// Mitsubishi GX Works2 project: PJT07_12_PLC02変更後(20220606_01)   PLC: Q03UDV

FUNCTION_BLOCK Alarm_FB
VAR_INPUT
  IB_Alarm : BOOL;  (* 入力@警報発生(0:-/1:発生) *)
END_VAR
VAR
  VT_AlarmDelayTimer : TIMER;  (* 内部@異常入力ﾃﾞｨﾚｲﾀｲﾏ *)
END_VAR
VAR_INPUT
  IW_DelayTimerVal : INT;  (* 入力@ﾃﾞｨﾚｲﾀｲﾏ値 *)
END_VAR
VAR_OUTPUT
  OB_AlarmHolding : BOOL;  (* 出力@ｱﾗｰﾑ自己保持(0:-/1:保持) *)
END_VAR
VAR_INPUT
  IB_AlarmResetPB : BOOL;  (* 入力@警報ﾘｾｯﾄPB(0:-/1:ﾘｾｯﾄ) *)
END_VAR
VAR
  VT_BuzzerStopTimer : TIMER;  (* 内部@ﾌﾞｻﾞｰｽﾄｯﾌﾟﾀｲﾏ *)
END_VAR
VAR_INPUT
  IW_BzStopTVal : INT;  (* 入力@ﾌﾞｻﾞｰｽﾄｯﾌﾟﾀｲﾏ値 *)
END_VAR
VAR
  VB_BuzzerStopFLG : BOOL;  (* 内部@ﾌﾞｻﾞｰｽﾄｯﾌﾟﾃﾞﾊﾞｲｽ(0:-/1:停止) *)
END_VAR
VAR_OUTPUT
  OB_DisplayFLG : BOOL;  (* 出力@ｱﾗｰﾑ表示ﾃﾞﾊﾞｲｽ(0:点滅/1:点灯) *)
END_VAR
VAR_INPUT
  IB_BuzzerStopPB : BOOL;  (* 入力@ﾌﾞｻﾞｰｽﾄｯﾌﾟPB(0:-/1:ｽﾄｯﾌﾟ) *)
END_VAR
VAR_OUTPUT
  OB_BuzzerFLG : BOOL;  (* 出力@ﾌﾞｻﾞｰﾌﾗｸﾞ *)
END_VAR
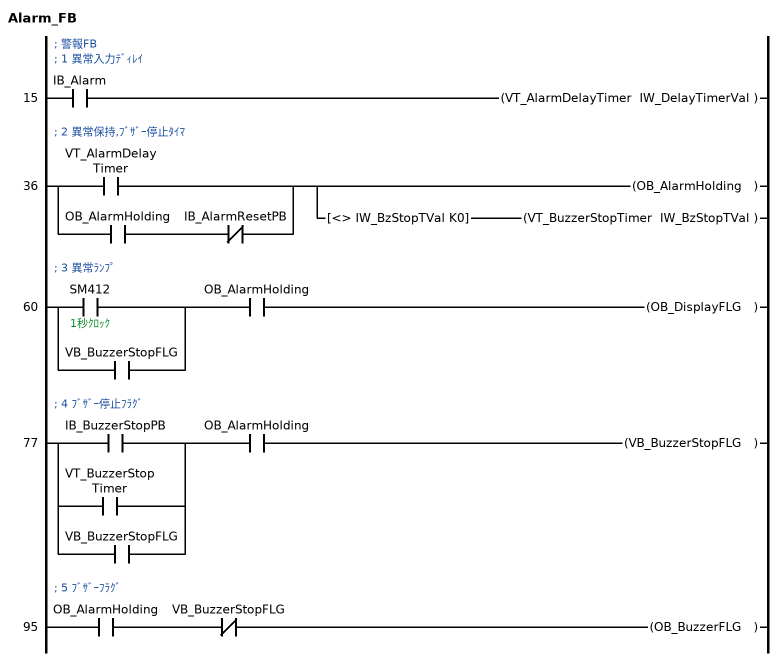
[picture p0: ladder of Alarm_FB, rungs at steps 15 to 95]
; 警報FB
; 1 異常入力ﾃﾞｨﾚｲ
15    LD      IB_Alarm
      OUT     VT_AlarmDelayTimer IW_DelayTimerVal
; 2 異常保持,ﾌﾞｻﾞｰ停止ﾀｲﾏ
36    LD      VT_AlarmDelayTimer
      LD      OB_AlarmHolding
      ANI     IB_AlarmResetPB
      ORB
      OUT     OB_AlarmHolding
      AND<>   IW_BzStopTVal K0
      OUT     VT_BuzzerStopTimer IW_BzStopTVal
; 3 異常ﾗﾝﾌﾟ
60    LD      SM412  ; 1秒ｸﾛｯｸ
      OR      VB_BuzzerStopFLG
      AND     OB_AlarmHolding
      OUT     OB_DisplayFLG
; 4 ﾌﾞｻﾞｰ停止ﾌﾗｸﾞ
77    LD      IB_BuzzerStopPB
      OR      VT_BuzzerStopTimer
      OR      VB_BuzzerStopFLG
      AND     OB_AlarmHolding
      OUT     VB_BuzzerStopFLG
; 5 ﾌﾞｻﾞｰﾌﾗｸﾞ
95    LD      OB_AlarmHolding
      ANI     VB_BuzzerStopFLG
      OUT     OB_BuzzerFLG
END_FUNCTION_BLOCK

PROGRAM 11_Alarm
VAR
  Alarm_FB_1 : Alarm_FB;
  Alarm_FB_2 : Alarm_FB;
END_VAR
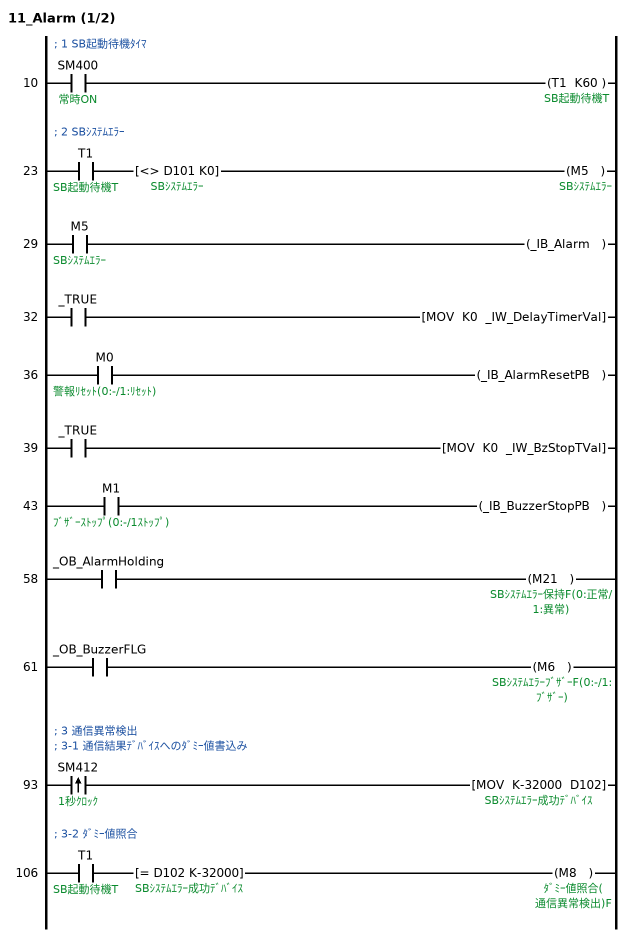
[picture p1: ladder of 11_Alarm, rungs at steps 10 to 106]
; 1 SB起動待機ﾀｲﾏ
10    LD      SM400  ; 常時ON
      OUT     T1 K60  ; SB起動待機T
; 2 SBｼｽﾃﾑｴﾗｰ
23    LD      T1  ; SB起動待機T
      AND<>   D101 K0  ; SBｼｽﾃﾑｴﾗｰ
      OUT     M5  ; SBｼｽﾃﾑｴﾗｰ
; FB BLK START Alarm_FB(Alarm_FB_1)
29    LD      M5  ; SBｼｽﾃﾑｴﾗｰ
      OUT     _IB_Alarm
32    LD      _TRUE
      MOV     K0 _IW_DelayTimerVal
36    LD      M0  ; 警報ﾘｾｯﾄ(0:-/1:ﾘｾｯﾄ)
      OUT     _IB_AlarmResetPB
39    LD      _TRUE
      MOV     K0 _IW_BzStopTVal
43    LD      M1  ; ﾌﾞｻﾞｰｽﾄｯﾌﾟ(0:-/1ｽﾄｯﾌﾟ)
      OUT     _IB_BuzzerStopPB
; FB START
; FB_NAME Alarm_FB
; INSTANCE_NAME Alarm_FB_1
; FB IN_B:IB_Alarm
; FB OUT_OB_AlarmHolding:B
; FB IN_W:IW_DelayTimerVal
; FB OUT_OB_DisplayFLG:B
; FB IN_B:IB_AlarmResetPB
; FB OUT_OB_BuzzerFLG:B
; FB IN_W:IW_BzStopTVal
; FB IN_B:IB_BuzzerStopPB
; FB END
58    LD      _OB_AlarmHolding
      OUT     M21  ; SBｼｽﾃﾑｴﾗｰ保持F(0:正常/1:異常)
61    LD      _OB_BuzzerFLG
      OUT     M6  ; SBｼｽﾃﾑｴﾗｰﾌﾞｻﾞｰF(0:-/1:ﾌﾞｻﾞｰ)
; FB BLK END
; 3 通信異常検出
; 3-1 通信結果ﾃﾞﾊﾞｲｽへのﾀﾞﾐｰ値書込み
93    LDP     SM412  ; 1秒ｸﾛｯｸ
      MOV     K-32000 D102  ; SBｼｽﾃﾑｴﾗｰ成功ﾃﾞﾊﾞｲｽ
; 3-2 ﾀﾞﾐｰ値照合
106   LD      T1  ; SB起動待機T
      AND=    D102 K-32000  ; SBｼｽﾃﾑｴﾗｰ成功ﾃﾞﾊﾞｲｽ
      OUT     M8  ; ﾀﾞﾐｰ値照合(通信異常検出)F
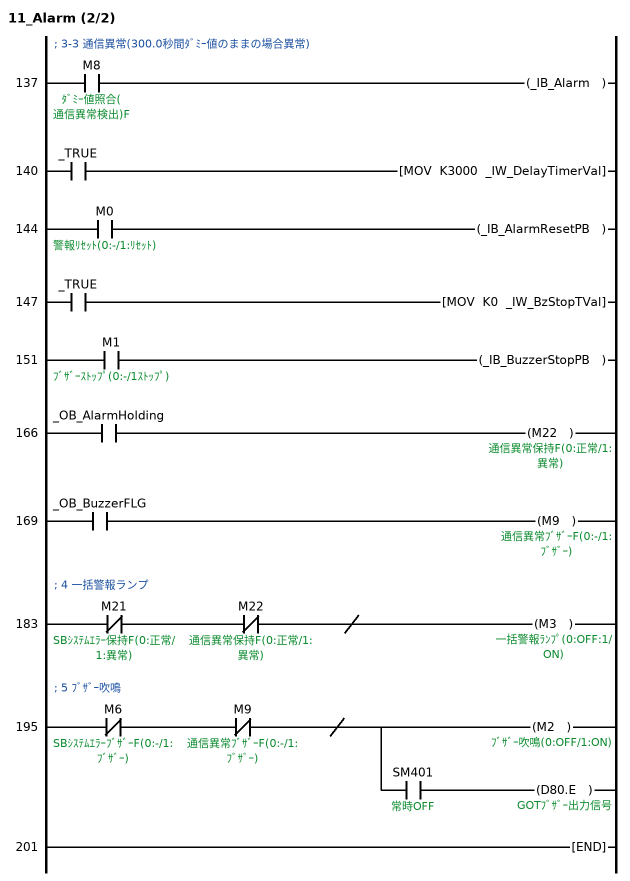
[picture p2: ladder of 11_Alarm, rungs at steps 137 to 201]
; FB BLK START Alarm_FB(Alarm_FB_2)
; 3-3 通信異常(300.0秒間ﾀﾞﾐｰ値のままの場合異常)
137   LD      M8  ; ﾀﾞﾐｰ値照合(通信異常検出)F
      OUT     _IB_Alarm
140   LD      _TRUE
      MOV     K3000 _IW_DelayTimerVal
144   LD      M0  ; 警報ﾘｾｯﾄ(0:-/1:ﾘｾｯﾄ)
      OUT     _IB_AlarmResetPB
147   LD      _TRUE
      MOV     K0 _IW_BzStopTVal
151   LD      M1  ; ﾌﾞｻﾞｰｽﾄｯﾌﾟ(0:-/1ｽﾄｯﾌﾟ)
      OUT     _IB_BuzzerStopPB
; FB START
; FB_NAME Alarm_FB
; INSTANCE_NAME Alarm_FB_2
; FB IN_B:IB_Alarm
; FB OUT_OB_AlarmHolding:B
; FB IN_W:IW_DelayTimerVal
; FB OUT_OB_DisplayFLG:B
; FB IN_B:IB_AlarmResetPB
; FB OUT_OB_BuzzerFLG:B
; FB IN_W:IW_BzStopTVal
; FB IN_B:IB_BuzzerStopPB
; FB END
166   LD      _OB_AlarmHolding
      OUT     M22  ; 通信異常保持F(0:正常/1:異常)
169   LD      _OB_BuzzerFLG
      OUT     M9  ; 通信異常ﾌﾞｻﾞｰF(0:-/1:ﾌﾞｻﾞｰ)
; FB BLK END
; 4 一括警報ランプ
183   LDI     M21  ; SBｼｽﾃﾑｴﾗｰ保持F(0:正常/1:異常)
      ANI     M22  ; 通信異常保持F(0:正常/1:異常)
      INV
      OUT     M3  ; 一括警報ﾗﾝﾌﾟ(0:OFF:1/ON)
; 5 ﾌﾞｻﾞｰ吹鳴
195   LDI     M6  ; SBｼｽﾃﾑｴﾗｰﾌﾞｻﾞｰF(0:-/1:ﾌﾞｻﾞｰ)
      ANI     M9  ; 通信異常ﾌﾞｻﾞｰF(0:-/1:ﾌﾞｻﾞｰ)
      INV
      OUT     M2  ; ﾌﾞｻﾞｰ吹鳴(0:OFF/1:ON)
      AND     SM401  ; 常時OFF
      OUT     D80.E  ; GOTﾌﾞｻﾞｰ出力信号
201   END
END_PROGRAM

PROGRAM 02_#2  // SB_Initial
VAR
  __IST_553ac48fffaf4984 : I+ST_553ac48fffaf4984;
END_VAR
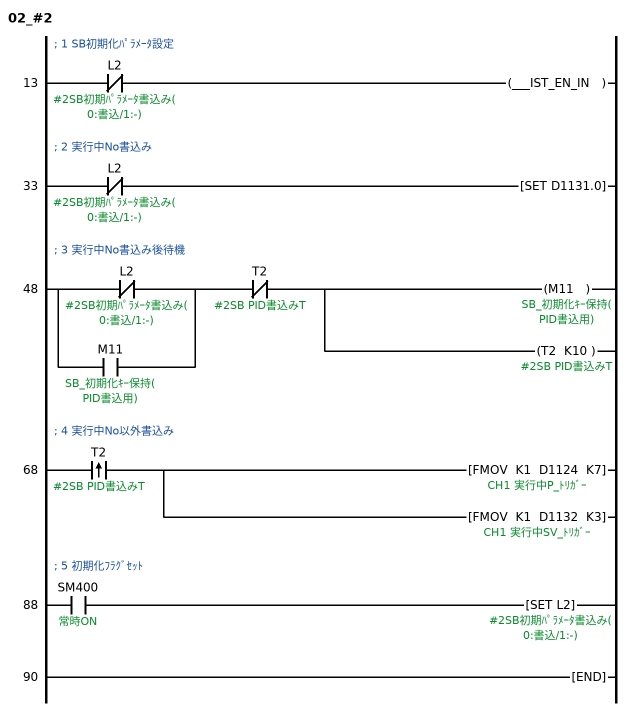
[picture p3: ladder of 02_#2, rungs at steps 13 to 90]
; FB BLK START I+ST_553ac48fffaf4984(__IST_553ac48fffaf4984)
; 1 SB初期化ﾊﾟﾗﾒｰﾀ設定
13    LDI     L2  ; #2SB初期ﾊﾟﾗﾒｰﾀ書込み(0:書込/1:-)
      OUT     ___IST_EN_IN
; FB START
; FB_NAME I+ST_553ac48fffaf4984
; INSTANCE_NAME __IST_553ac48fffaf4984
; FB IN_B:__IST_EN_IN
; FB OUT___IST_EN_OUT:B
; FB END
; FB BLK END
; 2 実行中No書込み
33    LDI     L2  ; #2SB初期ﾊﾟﾗﾒｰﾀ書込み(0:書込/1:-)
      SET     D1131.0
; 3 実行中No書込み後待機
48    LDI     L2  ; #2SB初期ﾊﾟﾗﾒｰﾀ書込み(0:書込/1:-)
      OR      M11  ; SB_初期化ｷｰ保持(PID書込用)
      ANI     T2  ; #2SB PID書込みT
      OUT     M11  ; SB_初期化ｷｰ保持(PID書込用)
      OUT     T2 K10  ; #2SB PID書込みT
; 4 実行中No以外書込み
68    LDP     T2  ; #2SB PID書込みT
      FMOV    K1 D1124 K7  ; CH1 実行中P_ﾄﾘｶﾞｰ
      FMOV    K1 D1132 K3  ; CH1 実行中SV_ﾄﾘｶﾞｰ
; 5 初期化ﾌﾗｸﾞｾｯﾄ
88    LD      SM400  ; 常時ON
      SET     L2  ; #2SB初期ﾊﾟﾗﾒｰﾀ書込み(0:書込/1:-)
90    END
END_PROGRAM

PROGRAM 22_#2  // SB100
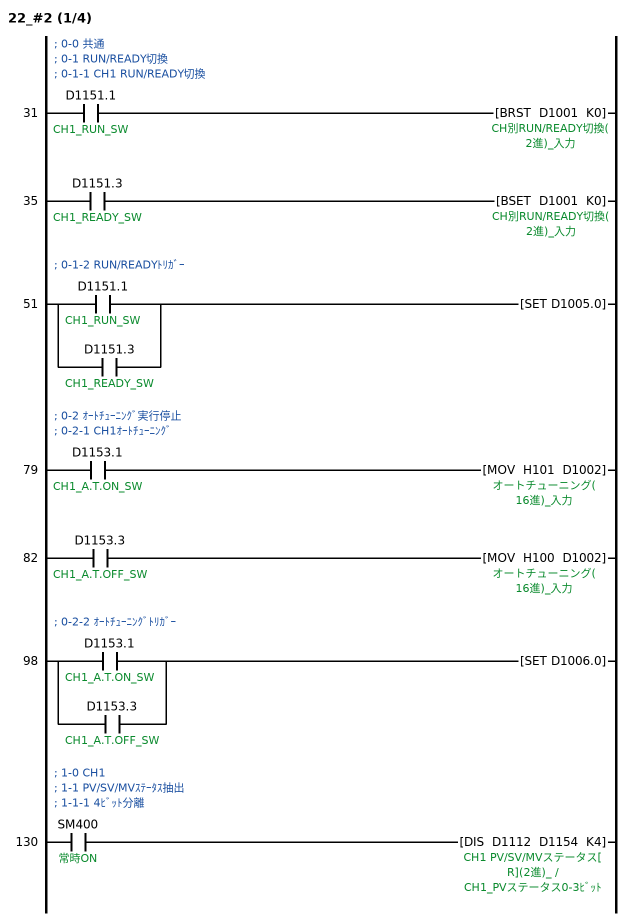
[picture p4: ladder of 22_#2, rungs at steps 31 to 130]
; 0-0 共通
; 0-1 RUN/READY切換
; 0-1-1 CH1 RUN/READY切換
31    LD      D1151.1  ; CH1_RUN_SW
      BRST    D1001 K0  ; CH別RUN/READY切換(2進)_入力
35    LD      D1151.3  ; CH1_READY_SW
      BSET    D1001 K0
; 0-1-2 RUN/READYﾄﾘｶﾞｰ
51    LD      D1151.1  ; CH1_RUN_SW
      OR      D1151.3  ; CH1_READY_SW
      SET     D1005.0
; 0-2 ｵｰﾄﾁｭｰﾆﾝｸﾞ実行停止
; 0-2-1 CH1ｵｰﾄﾁｭｰﾆﾝｸﾞ
79    LD      D1153.1  ; CH1_A.T.ON_SW
      MOV     H101 D1002  ; オートチューニング(16進)_入力
82    LD      D1153.3  ; CH1_A.T.OFF_SW
      MOV     H100 D1002
; 0-2-2 ｵｰﾄﾁｭｰﾆﾝｸﾞﾄﾘｶﾞｰ
98    LD      D1153.1  ; CH1_A.T.ON_SW
      OR      D1153.3  ; CH1_A.T.OFF_SW
      SET     D1006.0
; 1-0 CH1
; 1-1 PV/SV/MVｽﾃｰﾀｽ抽出
; 1-1-1 4ﾋﾞｯﾄ分離
130   LD      SM400  ; 常時ON
      DIS     D1112 D1154 K4  ; CH1 PV/SV/MVステータス[R](2進)_ / CH1_PVステータス0-3ﾋﾞｯﾄ
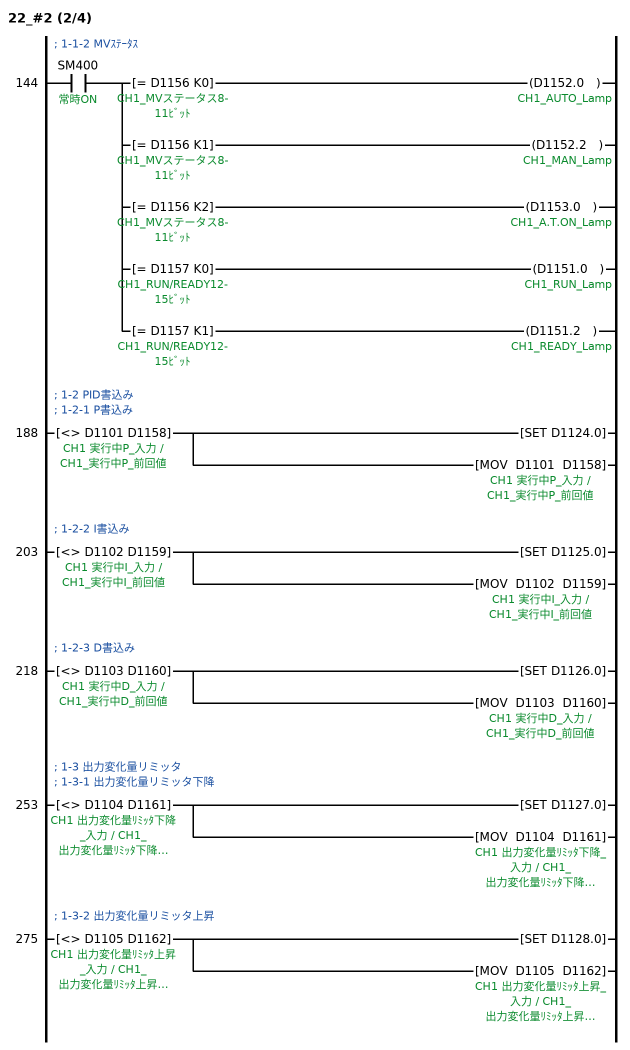
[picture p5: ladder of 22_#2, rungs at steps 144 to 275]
; 1-1-2 MVｽﾃｰﾀｽ
144   LD      SM400  ; 常時ON
      MPS
      AND=    D1156 K0  ; CH1_MVステータス8-11ﾋﾞｯﾄ
      OUT     D1152.0  ; CH1_AUTO_Lamp
      MRD
      AND=    D1156 K1  ; CH1_MVステータス8-11ﾋﾞｯﾄ
      OUT     D1152.2  ; CH1_MAN_Lamp
      MRD
      AND=    D1156 K2  ; CH1_MVステータス8-11ﾋﾞｯﾄ
      OUT     D1153.0  ; CH1_A.T.ON_Lamp
      MRD
      AND=    D1157 K0  ; CH1_RUN/READY12-15ﾋﾞｯﾄ
      OUT     D1151.0  ; CH1_RUN_Lamp
      MPP
      AND=    D1157 K1  ; CH1_RUN/READY12-15ﾋﾞｯﾄ
      OUT     D1151.2  ; CH1_READY_Lamp
; 1-2 PID書込み
; 1-2-1 P書込み
188   LD<>    D1101 D1158  ; CH1 実行中P_入力 / CH1_実行中P_前回値
      SET     D1124.0
      MOV     D1101 D1158
; 1-2-2 I書込み
203   LD<>    D1102 D1159  ; CH1 実行中I_入力 / CH1_実行中I_前回値
      SET     D1125.0
      MOV     D1102 D1159
; 1-2-3 D書込み
218   LD<>    D1103 D1160  ; CH1 実行中D_入力 / CH1_実行中D_前回値
      SET     D1126.0
      MOV     D1103 D1160
; 1-3 出力変化量リミッタ
; 1-3-1 出力変化量リミッタ下降
253   LD<>    D1104 D1161  ; CH1 出力変化量ﾘﾐｯﾀ下降_入力 / CH1_出力変化量ﾘﾐｯﾀ下降_前回値
      SET     D1127.0
      MOV     D1104 D1161
; 1-3-2 出力変化量リミッタ上昇
275   LD<>    D1105 D1162  ; CH1 出力変化量ﾘﾐｯﾀ上昇_入力 / CH1_出力変化量ﾘﾐｯﾀ上昇_前回値
      SET     D1128.0
      MOV     D1105 D1162
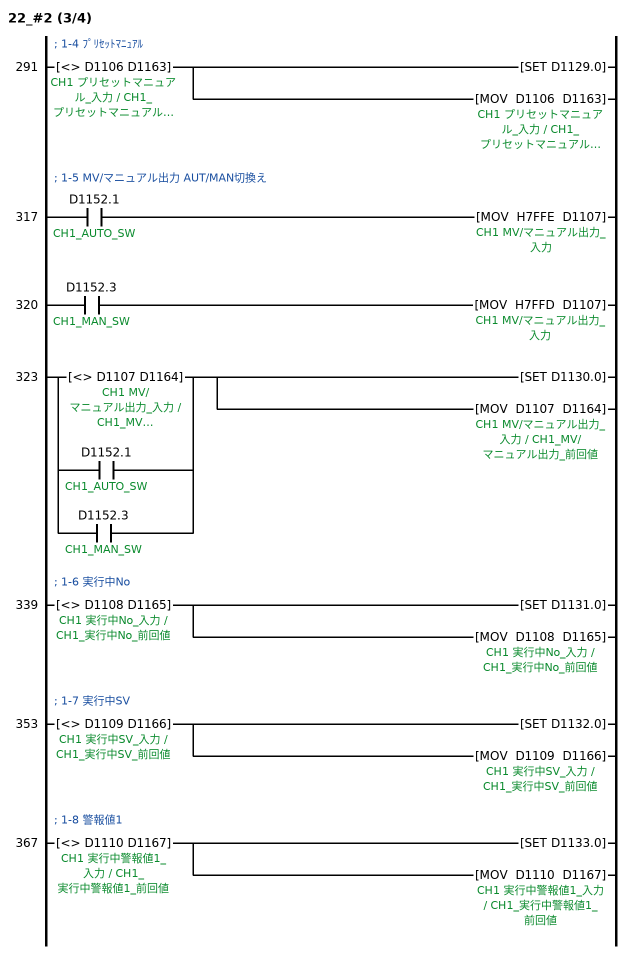
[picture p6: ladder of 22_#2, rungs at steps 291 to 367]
; 1-4 ﾌﾟﾘｾｯﾄﾏﾆｭｱﾙ
291   LD<>    D1106 D1163  ; CH1 プリセットマニュアル_入力 / CH1_プリセットマニュアル_前回値
      SET     D1129.0
      MOV     D1106 D1163
; 1-5 MV/マニュアル出力 AUT/MAN切換え
317   LD      D1152.1  ; CH1_AUTO_SW
      MOV     H7FFE D1107  ; CH1 MV/マニュアル出力_入力
320   LD      D1152.3  ; CH1_MAN_SW
      MOV     H7FFD D1107
323   LD<>    D1107 D1164  ; CH1 MV/マニュアル出力_入力 / CH1_MV/マニュアル出力_前回値
      OR      D1152.1  ; CH1_AUTO_SW
      OR      D1152.3  ; CH1_MAN_SW
      SET     D1130.0
      MOV     D1107 D1164
; 1-6 実行中No
339   LD<>    D1108 D1165  ; CH1 実行中No_入力 / CH1_実行中No_前回値
      SET     D1131.0
      MOV     D1108 D1165
; 1-7 実行中SV
353   LD<>    D1109 D1166  ; CH1 実行中SV_入力 / CH1_実行中SV_前回値
      SET     D1132.0
      MOV     D1109 D1166
; 1-8 警報値1
367   LD<>    D1110 D1167  ; CH1 実行中警報値1_入力 / CH1_実行中警報値1_前回値
      SET     D1133.0
      MOV     D1110 D1167
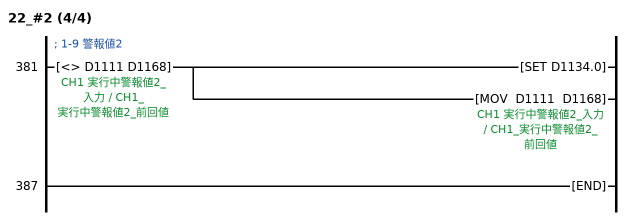
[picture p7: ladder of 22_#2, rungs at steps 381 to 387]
; 1-9 警報値2
381   LD<>    D1111 D1168  ; CH1 実行中警報値2_入力 / CH1_実行中警報値2_前回値
      SET     D1134.0
      MOV     D1111 D1168
387   END
END_PROGRAM

FUNCTION_BLOCK I+ST_553ac48fffaf4984
VAR_INPUT
  __IST_EN_IN : BOOL;
END_VAR
VAR_OUTPUT
  __IST_EN_OUT : BOOL;
END_VAR
(* IST HEADER START *)
IF NOT __IST_EN_IN THEN __IST_EN_OUT:=FALSE; RETURN; END_IF;
(* VERSION=1:TYPE=STB *)
(* IST HEADER END *)
D1101:=50;		(*CH1 実行中P*)
D1102:=60;		(*CH1 実行中I*)
D1103:=30;		(*CH1 実行中D*)
D1104:=0;		(*CH1 SV変化率下降*)
D1105:=0;		(*CH1 SV変化率上昇*)
D1106:=0;		(*CH1 プリセットマニュアル*)
D1108:=1;		(*CH1 実行中No*)
D1109:=234;		(*CH1 実行中SV*)
D1110:=30000;	(*CH1 実行中警報値1*)
D1111:=-30000;	(*CH1 実行中警報値2*)
END_FUNCTION_BLOCK

PROGRAM 01_SB  // Initial
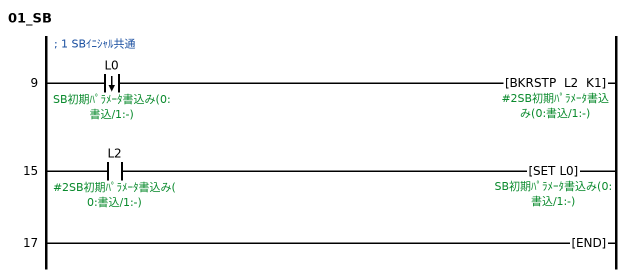
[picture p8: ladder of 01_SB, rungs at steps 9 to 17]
; 1 SBｲﾆｼｬﾙ共通
9     LDF     L0  ; SB初期ﾊﾟﾗﾒｰﾀ書込み(0:書込/1:-)
      BKRSTP  L2 K1  ; #2SB初期ﾊﾟﾗﾒｰﾀ書込み(0:書込/1:-)
15    LD      L2  ; #2SB初期ﾊﾟﾗﾒｰﾀ書込み(0:書込/1:-)
      SET     L0  ; SB初期ﾊﾟﾗﾒｰﾀ書込み(0:書込/1:-)
17    END
END_PROGRAM

// device comments not shown above
D71  ; GOTﾍﾞｰｽ画面
D72  ; GOTｵｰﾊﾞｰﾗｯﾌﾟｳｨﾝﾄﾞｳ
D73  ; GOTｽｰﾊﾟｰｲﾝﾎﾟｰｽﾞｳｨﾝﾄﾞｳ
D80  ; GOTｼｽﾃﾑ信号1-1
D81  ; GOTｼｽﾃﾑ信号2-1
D82  ; GOT数値入力番号
D83  ; GOT数値入力変更前値(32ﾋﾞｯﾄ)
D84  ; GOT数値入力変更前値(32ﾋﾞｯﾄ)
D85  ; GOT数値入力変更後値(32ﾋﾞｯﾄ)
D86  ; GOT数値入力変更後値(32ﾋﾞｯﾄ)
D87  ; GOTｴﾗｰｺｰﾄﾞ
D88  ; GOTｴﾗｰｺｰﾄﾞ2
D89  ; GOT印字中ﾚﾎﾟｰﾄ画面番号
D90  ; GOT表示中ﾍﾞｰｽ画面番号
D91  ; GOT表示中ｳｨﾝﾄﾞｳ1画面番号
D92  ; GOT現在ｶｰｿﾙ表示ｵﾌﾞｼﾞｪｸﾄID
D93  ; GOT前回ｶｰｿﾙ表示ｵﾌﾞｼﾞｪｸﾄID
D94  ; GOT現在ｶｰｿﾙ表示ﾕｰｻﾞID
D95  ; GOT前回ｶｰｿﾙ表示ﾕｰｻﾞID
D96  ; GOT入力ｷｰｺｰﾄﾞ
D97  ; GOT外部入出力機能･入力情報1
D98  ; GOT外部入出力機能･入力情報2
D103  ; SBｼｽﾃﾑｴﾗｰ失敗ﾃﾞﾊﾞｲｽ
D104  ; SBｼｽﾃﾑｴﾗｰｴﾗｰﾃﾞﾊﾞｲｽ
D1003  ; CH別RUN/READY切換(2進)_表示
D1004  ; オートチューニング(16進)_表示
D1005  ; CH別RUN/READY切換(2進)_ﾄﾘｶﾞｰ
D1006  ; オートチューニング(16進)_ﾄﾘｶﾞｰ
D1011  ; CH1PV_表示
D1012  ; CH2PV_表示
D1013  ; CH3PV_表示
D1014  ; CH4PV_表示
D1015  ; CH1SV_表示
D1016  ; CH2SV_表示
D1017  ; CH3SV_表示
D1018  ; CH4SV_表示
D1019  ; CH1MV_表示
D1020  ; CH2MV_表示
D1021  ; CH3MV_表示
D1022  ; CH4MV_表示
D1023  ; ALステータス1_表示
D1024  ; ALステータス2_表示
D1113  ; CH1 実行中P_表示
D1114  ; CH1 実行中I_表示
D1115  ; CH1 実行中D_表示
D1116  ; CH1 SV変化率下降_表示
D1117  ; CH1 SV変化率上昇_表示
D1118  ; CH1 プリセットマニュアル_表示
D1119  ; CH1 MV/マニュアル出力_表示
D1120  ; CH1 実行中No_表示
D1121  ; CH1 実行中SV_表示
D1122  ; CH1 実行中警報値1_表示
D1123  ; CH1 実行中警報値2_表示
D1125  ; CH1 実行中I_ﾄﾘｶﾞｰ
D1126  ; CH1 実行中D_ﾄﾘｶﾞｰ
D1127  ; CH1 出力変化量ﾘﾐｯﾀ下降_ﾄﾘｶﾞｰ
D1128  ; CH1 出力変化量ﾘﾐｯﾀ上昇_ﾄﾘｶﾞｰ
D1129  ; CH1 プリセットマニュアル_ﾄﾘｶﾞｰ
D1130  ; CH1 MV/マニュアル出力_ﾄﾘｶﾞｰ
D1131  ; CH1 実行中No_ﾄﾘｶﾞｰ
D1133  ; CH1 実行中警報値1_ﾄﾘｶﾞｰ
D1134  ; CH1 実行中警報値2_ﾄﾘｶﾞｰ
D1151  ; CH1_RUNREADY
D1152  ; CH1_AUTOMAN
D1153  ; CH1_A.T
D1155  ; CH1_SVステータス4-7ﾋﾞｯﾄ
D80.0  ; GOT自動ｽｸﾘｰﾝｾｰﾌﾞ無効信号
D80.1  ; GOT強制ｽｸﾘｰﾝｾｰﾌﾞ番号
D80.2  ; GOT強制ｽｸﾘｰﾝｾｰﾌﾞﾀｯﾁ解除信号
D80.3  ; GOT入力ｷｰ読出し完了信号
D80.4  ; GOT数値入力読出し完了信号
D80.5  ; GOTﾊﾞｰｺｰﾄﾞ入力無効信号(CH8)
D80.6  ; GOT外部機器入出力完了信号(CH8)
D80.7  ; GOT使用禁止
D80.8  ; GOTﾌﾞｻﾞｰｽﾘｰｼｮｯﾄ出力信号
D80.9  ; GOTﾀｯﾁ操作無効信号
D80.A  ; GOTﾊｰﾄﾞｺﾋﾟｰ設定有効信号
D80.B  ; GOT使用禁止
D80.C  ; GOTﾊｰﾄﾞｺﾋﾟｰ白黒反転信号
D80.D  ; GOTｴﾗｰﾘｾｯﾄ信号
D80.F  ; GOTﾌﾞｻﾞｰﾜﾝｼｮｯﾄ出力信号
D1023.0  ; CH1_AL1_表示
D1023.2  ; CH1_AL2_表示
D1023.4  ; CH1_AL3_表示
D1023.6  ; CH1_AL4_表示
D1023.8  ; CH2_AL1_表示
D1023.A  ; CH2_AL2_表示
D1023.C  ; CH2_AL3_表示
D1023.E  ; CH2_AL4_表示
D1024.0  ; CH3_AL1_表示
D1024.2  ; CH3_AL2_表示
D1024.4  ; CH3_AL3_表示
D1024.6  ; CH3_AL4_表示
D1024.8  ; CH4_AL1_表示
D1024.A  ; CH4_AL2_表示
D1024.C  ; CH4_AL3_表示
D1024.E  ; CH4_AL4_表示
D1153.2  ; CH1_A.T.OFF_Lamp
